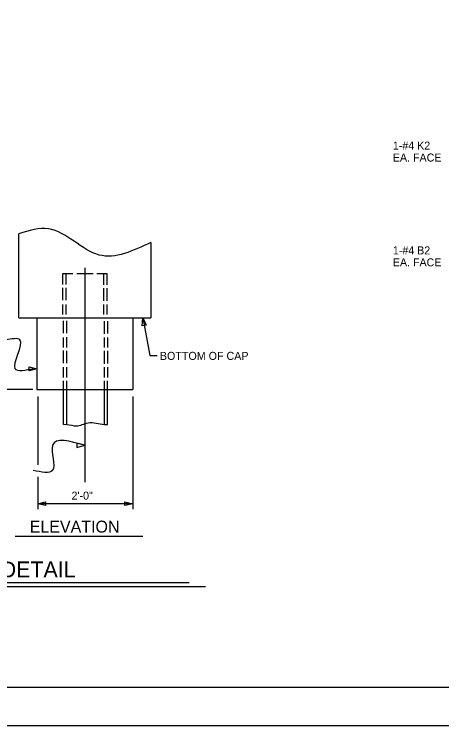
# Model space of a CAD drawing. Extents: x -41 to 191, y -168 to 6.
# Drawn here: x 25.32 to 40.65, y -168.43 to -142.92 of the extents above; entities that cross this region are included whole.
import ezdxf

# ---------------------------------------------------------------- set-up
doc = ezdxf.new("R2010")
doc.units = 0
for name, color, linetype in [('Arrowhead Terminators CELL', 7, 'Continuous'), ('Default', 7, 'Continuous'), ('Dimension Lines', 7, 'Continuous'), ('Dimension Lines CELL', 7, 'Continuous'), ('Mis Center Lines', 7, 'Continuous'), ('Mis Object Lines', 7, 'Continuous'), ('Plan Sheet CELL', 7, 'Continuous'), ('Plot Shape CELL', 7, 'Continuous'), ('Structural Steel Lines CELL', 7, 'Continuous'), ('Subtitle Text', 7, 'Continuous'), ('Text', 7, 'Continuous'), ('Text CELL', 7, 'Continuous'), ('Title Text', 7, 'Continuous')]:
    doc.layers.add(name, color=color, linetype=linetype)

msp = doc.modelspace()

# ---------------------------------------------------------------- linework, layer by layer
at = {"layer": 'Arrowhead Terminators CELL'}
for points in [[(29.924, -153.801), (30.048, -154.068), (29.907, -154.095)], [(26.134, -155.631), (25.849, -155.703), (25.849, -155.56)], [(27.853, -158.375), (27.567, -158.304), (27.567, -158.447)], [(26.159, -160.467), (26.445, -160.395), (26.445, -160.538)], [(29.572, -160.467), (29.286, -160.538), (29.286, -160.395)]]:
    msp.add_lwpolyline(points, close=True, dxfattribs=at)
at = {"layer": 'Default'}
for p, q in [((26.134, -153.801), (26.134, -156.379)), ((29.572, -153.801), (29.572, -156.379)), ((26.134, -156.379), (29.572, -156.379))]:
    msp.add_line(p, q, dxfattribs=at)
at = {"layer": 'Dimension Lines'}
for p, q in [((26.159, -156.623), (26.159, -159.07)), ((29.572, -156.623), (29.572, -160.665)), ((26.159, -159.501), (26.159, -160.665)), ((29.572, -160.467), (26.159, -160.467))]:
    msp.add_line(p, q, dxfattribs=at)
msp.add_lwpolyline([(29.924, -153.801), (30.184, -155.157), (30.443, -155.157)], dxfattribs=at)
at = {"layer": 'Dimension Lines CELL'}
msp.add_line((25.986, -156.379), (21.962, -156.379), dxfattribs=at)
for points in [[(26.009, -155.631), (25.356, -155.631), (25.523, -154.598), (25.004, -154.598)], [(27.853, -158.375), (26.692, -158.375), (26.692, -159.272), (25.999, -159.272)]]:
    msp.add_spline(points, degree=3, dxfattribs=at)
at = {"layer": 'Mis Center Lines'}
msp.add_line((27.853, -152.01), (27.853, -159.695), dxfattribs=at)
at = {"layer": 'Mis Object Lines'}
for p, q in [((25.489, -153.801), (25.489, -150.792)), ((30.217, -151.104), (30.217, -153.801)), ((25.489, -153.801), (30.217, -153.801))]:
    msp.add_line(p, q, dxfattribs=at)
msp.add_spline([(30.217, -151.104), (28.365, -151.552), (26.549, -150.613), (25.489, -150.792)], degree=3, dxfattribs=at)
at = {"layer": 'Plan Sheet CELL'}
msp.add_line((2.412, -167.042), (75.628, -167.042), dxfattribs=at)
at = {"layer": 'Plot Shape CELL'}
msp.add_lwpolyline([(0, -118.093), (75.648, -118.093), (75.648, -168.429), (0, -168.429)], close=True, dxfattribs=at)
at = {"layer": 'Structural Steel Lines CELL'}
for p, q in [((27.183, -152.608), (27.183, -152.219)), ((28.528, -152.626), (28.528, -152.219)), ((27.183, -153.174), (27.183, -152.733)), ((28.528, -153.196), (28.528, -152.737)), ((27.183, -153.687), (27.183, -153.321)), ((28.528, -153.687), (28.528, -153.325)), ((27.207, -154.356), (27.207, -153.915)), ((28.552, -154.378), (28.552, -153.919)), ((27.207, -154.868), (27.207, -154.503)), ((28.552, -154.868), (28.552, -154.507)), ((27.207, -155.426), (27.207, -154.985)), ((28.552, -155.448), (28.552, -154.989)), ((27.207, -155.938), (27.207, -155.573)), ((28.552, -155.938), (28.552, -155.577)), ((27.09, -157.623), (27.09, -156.057)), ((27.207, -157.623), (27.207, -156.057)), ((28.552, -157.623), (28.552, -156.057)), ((28.667, -157.623), (28.667, -156.057))]:
    msp.add_line(p, q, dxfattribs=at)
for points in [[(27.065, -152.611), (27.065, -152.219), (27.425, -152.219)], [(27.566, -152.219), (28.15, -152.219)], [(28.282, -152.219), (28.641, -152.219), (28.641, -152.617)], [(27.065, -153.175), (27.065, -152.729)], [(28.641, -152.74), (28.641, -153.19)], [(27.065, -153.687), (27.065, -153.324)], [(28.641, -153.324), (28.641, -153.687)], [(27.09, -154.357), (27.09, -153.911)], [(28.665, -153.922), (28.665, -154.371)], [(27.09, -154.868), (27.09, -154.506)], [(28.665, -154.506), (28.665, -154.868)], [(27.09, -155.427), (27.09, -154.981)], [(28.665, -154.992), (28.665, -155.441)], [(27.09, -155.938), (27.09, -155.576)], [(28.665, -155.576), (28.665, -155.938)]]:
    msp.add_lwpolyline(points, dxfattribs=at)
msp.add_spline([(27.09, -157.623), (27.207, -157.623), (27.547, -157.68), (27.966, -157.565), (28.552, -157.623), (28.667, -157.623)], degree=3, dxfattribs=at)
at = {"layer": 'Subtitle Text'}
msp.add_line((29.929, -161.647), (25.358, -161.647), dxfattribs=at)
at = {"layer": 'Text CELL'}
for p, q in [((6.767, -163.431), (32.173, -163.431)), ((7.321, -163.287), (31.592, -163.287))]:
    msp.add_line(p, q, dxfattribs=at)

# ---------------------------------------------------------------- texts
at = {"layer": 'Subtitle Text'}
msp.add_text('ELEVATION', height=0.4286, rotation=360, dxfattribs=at).set_placement((25.875, -161.504))
at = {"layer": 'Text'}
for s, height, p in [('BOTTOM OF CAP', 0.28702, (30.54, -155.312)), ('2\'-0"', 0.287, (27.372, -160.322))]:
    msp.add_text(s, height=height, rotation=360, dxfattribs=at).set_placement(p)
at = {"layer": 'Text CELL'}
for s, p in [('1-#4 K2', (38.892, -147.772)), ('EA. FACE', (38.892, -148.201)), ('1-#4 B2', (38.892, -151.529)), ('EA. FACE', (38.892, -151.958))]:
    msp.add_text(s, height=0.2859, dxfattribs=at).set_placement(p)
at = {"layer": 'Title Text'}
msp.add_text('CORROSION PROTECTION FOR STEEL PILES DETAIL', height=0.57403, dxfattribs=at).set_placement((7.772, -163.113))

doc.saveas('drawing.dxf')
